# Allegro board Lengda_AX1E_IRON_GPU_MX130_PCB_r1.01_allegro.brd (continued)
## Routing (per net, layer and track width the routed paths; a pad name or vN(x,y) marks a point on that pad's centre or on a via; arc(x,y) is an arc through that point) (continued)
GNDS_SENSE: length 0.6
  TOP w0.102: U3.F3 v1(32.98,37.8)
VDD_GPU: length 27.7
  L3 w0.305: v1(67.46,46.82) 67.59,46.69 67.59,44.89 67.88,44.6 69.67,44.6 71.26,46.18 71.26,60.58 68.81,63.04 v1(66.15,63.04)
  BOTTOM w0.203: R739.1 v1(67.46,46.82)
VDD_GPU_AON: length 195.1
  TOP w0.305: R257.2 21.52,29.05 21.66,28.9 R619.2 R622.2 R643.1 ; R640.1 v1(28.26,32.34) ; R643.1 v1(21.42,27.34) ; R643.1 R617.1
  L3 w0.305: v1(21.42,27.34) 23.16,27.34 25.32,25.18 25.32,17.68 28.01,14.99 36.69,14.99 37.02,14.66 42,14.66 v1(42.09,14.75) 42.2,14.86 47.75,14.86 49.64,12.97 61.52,12.97 62.6,11.89 v1(63.04,11.89) 63.04,17.32 64.2,18.47 64.2,24.52 63.64,25.08 63.64,34.78 66.03,37.17 66.03,42.18 v1(65.44,42.77)
  L6 w0.305: v1(21.42,27.34) 21.02,26.93 19.66,26.93 16.66,23.93 v1(16.66,9.66) ; v1(63.59,56.58) 63.02,56.58 59.84,53.41 59.84,50.96 59.46,50.58 v1(59.28,50.58) 59.28,50.28 59.68,49.89 59.68,47.34 64.25,42.77 v1(65.44,42.77)
  BOTTOM w0.203: R637.1 59.28,50.58 v1(59.28,50.58) ; R647.1 65.27,42.6 v1(65.44,42.77)
  BOTTOM w0.254: v1(21.42,27.34) 22.16,26.6 R642.1
  BOTTOM w0.305: Q36.1 22.68,24.49 22.91,24.72 R645.1 ; Q36.1 23.07,23.35 24.12,22.31 25.2,22.31 25.63,22.74 25.63,25.44 26.79,26.61 R601.2 26.98,28.67 R602.1 27.87,29.56 R636.1 27.87,31.95 v1(28.26,32.34) ; Q36.1 21.09,23.35 20.76,23.68 20.76,26.68 v1(21.42,27.34) 22,27.91 22,29.43 22.26,29.7 Q35.1 ; Q35.1 24.37,29.7 R615.1 ; Q35.1 23.2,30.68 24.02,31.51 R631.2 R641.2 24.23,32.81 21.82,32.81 21.41,33.21 Q34.1 21.41,34.74 21.8,35.13 R614.1 ; v1(42.09,14.75) 41.82,15.02 R37.1 41.39,16.62 40.94,17.08 R41.1 ; R599.1 R594.1 v1(16.66,9.66) ; 62.48,60.06 62.22,60.33 ; 62.22,60.33 62.48,60.33 ; 62.22,60.33 62.2,60.33 ; R100.1 63.28,11.66 v1(63.04,11.89) ; R251.2 31.05,30.07 28.78,32.34 v1(28.26,32.34) ; v1(28.26,32.34) 28.26,32.78 R635.1 27.83,33.21 R634.1 27.84,34.09 R638.1 R639.1 ; 62.2,60.33 62.47,60.6 ; 62.2,60.33 61.85,60.33 61.57,60.61 R750.1
VDD_GPU_MAIN: length 191.7
  TOP w0.305: R28.2 18.57,25.95 v1(19.54,24.98) ; R754.1 v1(60.79,57.81)
  L3 w0.305: v1(19.54,24.98) 19.79,24.73 19.79,21.06 22.31,18.53 22.31,14.59 27.15,9.75 31.28,9.75 32.66,11.13 37.24,11.13 38.06,10.31 40.86,10.31 41.53,10.98 43.84,10.98 45.27,9.56 60.24,9.56 v1(60.31,9.63)
  L3 w0.508: v1(43.23,20.33) 43.46,20.1 45.19,20.1 45.2,20.08 53.63,20.08 54.1,20.55 54.1,22.34 61.28,29.52 61.28,33.61 60.83,34.05 59.12,34.05 58.41,34.77 58.41,38.21 59.46,39.26 59.46,45.99 56.88,48.57 56.88,51.63 59.94,54.69 59.94,57.1 v1(60.3,57.46)
  L6 w0.305: v1(28.36,26.73) 26.61,24.98 v1(19.54,24.98)
  BOTTOM w0.305: v1(19.54,24.98) R479.2 17,25.48 16.24,26.23 14.69,26.23 12.43,23.97 12.43,21.07 12.87,20.64 R480.2 C863.1 U36.8 14.46,13.79 R481.2 14.33,10.95 15.09,10.19 R593.1 15.87,9.58 16.38,9.06 17.69,9.06 18.23,9.6 R598.1 ; Q6.1 60.92,9.03 v1(60.31,9.63) ; R250.2 28.37,26.73 v1(28.36,26.73)
  BOTTOM w0.508: R250.2 33.93,23.9 37.5,20.33 v1(43.23,20.33) 43.24,20.33 49.16,26.24 49.16,34.19 47.79,35.57 R154.2
VDDS_SENSE: length 0.6
  TOP w0.102: U3.F4 v1(32.98,38.6)
1.5S_LGATE: length 2.5
  BOTTOM w0.305: U37.9 11.48,36.29
  BOTTOM w0.635: 11.48,36.29 10.97,36.8 R701.1
1.5S_UGATE: length 2.6
  BOTTOM w0.305: U37.13 14.35,36.29 14.49,36.43
  BOTTOM w0.635: R698.1 15.42,37.36 14.49,36.43
+VSYS_DCIN: length 3.7
  BOTTOM w0.4: 71.03,37.01 71.5,37.48 ; 71.52,37.01 71.03,37.01 71.59,36.45
  BOTTOM w0.406: GR1.2 70.42,37.81 GC1.1 71.03,37.01
  vias: v2(68.03,13.44) v2(68.05,12.67) v2(68.83,13.44) v2(68.82,12.68) v2(72.99,63.47) v2(72.97,62.73) v2(73.8,63.47) v2(73.8,62.73)
CLK_GPU_OE#: length 2.6
  BOTTOM w0.102: R153.2 59.25,7.71 Q6.3 57.72,7.71 GR5.2
CLK_PCIE_GPU_N: length 50.9
  TOP w0.109: U3.AD8 v1(47.86,42.76)
  L3 w0.087: v1(47.86,42.76) 48.2,42.44 48.29,42.45 49.8,42.45 50.3,41.95 55.14,41.95 v1(55.36,42.16)
  BOTTOM w0.109: v1(55.36,42.16) 55.4,42.12 55.87,42.12 56.22,41.76 56.22,39.73 55.25,38.76 55.25,22.73 56.22,21.75 56.22,6.52 55.91,6.2 55.91,2.9 56.05,2.76 GCN1.11
CLK_PCIE_GPU_P: length 50.9
  TOP w0.109: U3.AE8 v1(47.89,41.92)
  L3 w0.087: v1(55.36,41.59) 55.18,41.76 50.23,41.76 49.73,42.26 48.3,42.26 48.21,42.26 v1(47.89,41.92)
  BOTTOM w0.109: v1(55.36,41.59) 55.67,41.9 55.78,41.9 56,41.67 56,39.82 55.03,38.85 55.03,22.64 56,21.66 56,6.61 55.69,6.29 55.69,2.95 55.59,2.85 55.36,2.85 55.25,2.74 GCN1.13
EMC_THERM#: length 1.6
  TOP w0.203: U2.4 29.5,25.59 29.86,25.96 R27.1
FAN_BACK_GPU: length 7.4
  TOP w0.254: GCN9.2 v1(9.37,77.21)
  BOTTOM w0.305: GR428.2 GR429.2 ; GR429.2 10.18,77.35 10.6,77.77 GD10.P ; GR429.2 v1(9.37,77.21)
FAN_PWMIN_GPU: length 126.7
  TOP w0.102: GCN1.4 58.85,2.37 59.27,2.79 v1(59.27,3.32)
  TOP w0.254: GCN9.3 v1(9.45,78.21)
  L3 w0.203: v1(59.27,3.32) 59.12,3.47 57.71,3.47 55.51,5.67 49.91,5.67 48.4,4.16 40.3,4.16 39.38,5.07 17.28,5.07 12.84,9.52 12.84,21.06 7.85,26.05 7.85,30.07 8.99,31.21 8.99,35.41 10.68,37.1 10.68,51.75 11.57,52.63 11.57,66.67 10.74,67.49 10.74,76.91 v1(9.45,78.21)
FAN_VCC_GPU: length 3.2
  TOP w0.406: GCN9.1 v1(9.26,76.21)
  BOTTOM w0.508: v1(9.26,76.21) GC317.2 GFB11.1
FB_CAL_PD_VDDQ: length 6.5
  TOP w0.135: U3.D22 v1(31.3,54.32)
  BOTTOM w0.102: v1(31.3,54.32) 31.07,54.32 30.67,53.92 28.59,53.92 27.15,55.35 R246.2
FB_CAL_PU_GND: length 3.9
  TOP w0.102: U3.C24 30.08,55.61 v1(29.69,56)
  BOTTOM w0.102: R247.2 27.39,56.63 28.36,56.63 28.6,56.39 29.29,56.39 29.69,56 v1(29.69,56)
FB_CAL_TERM_GND: length 2.3
  TOP w0.102: U3.B25 v1(28.88,56.81)
  BOTTOM w0.102: v1(28.88,56.81) 28.22,57.47 R248.2
FB_CLAMP: length 68
  L3 w0.102: v1(19.18,19.32) 19.18,13.37 25.16,7.38 41.1,7.38 41.95,6.53 46.85,6.53 48.11,7.79 58.18,7.79 v1(59.04,6.93)
  BOTTOM w0.102: R600.2 Q25.3 26.33,21.35 25.91,21.77 21.4,21.77 19.18,19.55 v1(19.18,19.32) ; GCN1.3 59.25,2.54 60.05,3.33 60.05,5.92 v1(59.04,6.93)
FB_PLLAVDD: length 1.8
  TOP w0.3: v1(32.88,49.32) 32.88,49.3 U3.F16
  TOP w0.305: v1(39.08,53.27) 39.08,53.85 U3.P22 ; U3.H22 v1(34.57,53.61)
  vias: v1(49.62,54.99)
FB_VREF: length 1.6
  TOP w0.135: U3.D23 v1(30.47,54.34)
  BOTTOM w0.102: TP1.1 30.08,54.34 v1(30.47,54.34)
FBA_CLK0: length 35.1
  TOP w0.127: R177.2 26.1,69.47 v1(26.22,69.59) ; M1.J12 v1(24.8,78.15) ; U3.D24 v1(30.48,55.99)
  L6 w0.104: v1(24.8,78.15) 24.8,78.33 24.87,78.4 25.19,78.4 25.98,77.6 25.98,75.27 26.99,74.26 26.99,71.23 26.47,70.72 26.47,69.84 v1(26.22,69.59)
  BOTTOM w0.127: v1(26.22,69.59) 26.42,69.43 26.42,68.83 28.95,66.29 28.95,64.23 28.82,64.11 27.27,64.11 26.99,63.83 26.99,63.38 27.24,63.13 28.82,63.13 28.95,63 28.95,62.75 28.82,62.62 27.27,62.62 26.99,62.34 26.99,61.89 27.24,61.64 28.82,61.64 28.95,61.52 28.95,60.01 30.09,58.87 30.09,56.57 30.48,56.18 v1(30.48,55.99) ; M1.J12 24.4,78.55 v1(24.8,78.15)
FBA_CLK0#: length 35.2
  TOP w0.127: M1.J11 v1(24.8,78.95) ; U3.D25 v1(30.48,56.81) ; R176.1 26.99,69.46 v1(26.84,69.61)
  L6 w0.104: v1(24.8,78.95) 24.8,78.69 24.88,78.61 25.27,78.61 26.19,77.69 26.19,75.35 27.2,74.35 27.2,71.14 26.68,70.63 26.68,69.77 v1(26.84,69.61)
  BOTTOM w0.127: M1.J11 24.8,78.95 v1(24.8,78.95) ; v1(26.84,69.61) 26.65,69.43 26.65,68.92 29.18,66.39 29.18,64.14 28.92,63.87 27.36,63.87 27.22,63.73 27.22,63.48 27.34,63.36 28.92,63.36 29.18,63.1 29.18,62.65 28.92,62.39 27.36,62.39 27.22,62.25 27.22,61.99 27.34,61.88 28.92,61.88 29.18,61.61 29.18,60.11 29.42,59.87 29.6,59.87 29.75,60.02 29.92,60.02 30.1,59.84 30.1,59.65 29.96,59.51 29.96,59.33 30.33,58.96 30.33,56.97 v1(30.48,56.81)
FBA_CLK1: length 45
  TOP w0.127: v1(59.45,78.96) 59.45,78.96 M2.J12 ; R14.2 57.36,67.55 57.36,67.31 v1(57.55,67.12) ; U3.N22 v1(38.76,54.4)
  L3 w0.104: v1(57.55,67.12) 57.33,67.33 57.33,75.84 58.26,76.77 58.26,77.53 59.18,78.45 59.18,78.69 v1(59.45,78.96)
  BOTTOM w0.127: v1(57.55,67.12) 57.42,66.99 57.42,65.83 55.68,64.09 42.15,64.09 38.85,60.79 38.85,59.3 37.47,57.92 37.47,55.84 38.51,54.79 38.51,54.52 38.63,54.4 v1(38.76,54.4) ; M2.J12 v1(59.45,78.96)
FBA_CLK1#: length 45.2
  TOP w0.127: v1(56.93,67.09) 57.12,67.29 57.12,67.55 R13.1 ; v1(58.66,78.95) 58.66,78.95 M2.J11 ; U3.M22 v1(37.94,54.38)
  L3 w0.104: v1(58.66,78.95) 58.97,78.64 58.97,78.53 58.05,77.62 58.05,76.86 57.12,75.93 57.12,67.29 v1(56.93,67.09)
  BOTTOM w0.127: v1(37.94,54.38) 38.18,54.38 38.28,54.48 38.28,54.69 37.23,55.74 37.23,58.02 38.61,59.4 38.61,60.89 42.05,64.33 55.58,64.33 57.18,65.93 57.18,66.84 v1(56.93,67.09) ; M2.J11 v1(58.66,78.95)
FBA_CMD0: length 23
  TOP w0.135: U3.C27 30.08,58.57 28.76,59.9 28.76,69.22 26.98,71 26.97,71 26.97,76.22 26.64,76.55 v1(24.8,76.55) M1.G12
  BOTTOM w0.135: M1.G12 v1(24.8,76.55)
FBA_CMD1: length 23.5
  TOP w0.135: M1.H10 v1(26.61,77.75) 27.39,76.97 27.39,71.26 29.45,69.21 29.45,59.84 30.45,58.83 30.45,57.57 U3.C26
  BOTTOM w0.135: M1.H10 v1(26.61,77.75)
FBA_CMD2: length 26
  TOP w0.135: M1.H11 25.55,77.41 v1(25.55,77.41) ; U3.E24 v1(31.34,56)
  BOTTOM w0.111: v1(31.34,56) 30.9,56.43 30.9,57.12 30.68,57.34
  BOTTOM w0.135: 30.68,57.34 30.68,67.14 27.06,70.76 27.06,77.07 26.78,77.35 25.61,77.35 v1(25.55,77.41) M1.H11
FBA_CMD3: length 29.2
  TOP w0.135: M1.K11 v1(25.6,78.96) ; U3.F24 v1(32.13,55.16)
  BOTTOM w0.111: 31.13,59.43 31.11,59.41 31.11,57.74 31.77,57.08 31.77,55.52 v1(32.13,55.16)
  BOTTOM w0.135: M1.K11 v1(25.6,78.96) 27.11,78.96 27.53,78.54 27.53,71.16 31.13,67.56 31.13,59.43
FBA_CMD4: length 24.4
  TOP w0.111: U3.D27 30.88,59.01 30.15,59.74
  TOP w0.135: 30.15,59.74 30.15,69.14 27.79,71.5 27.79,78.19 v1(26.62,79.36) M1.K10
  BOTTOM w0.135: M1.K10 v1(26.62,79.36)
FBA_CMD5: length 27.9
  TOP w0.111: U3.D26 31.28,57.6 31.28,58.16 31.22,58.22 31.22,59.24 30.75,59.74
  TOP w0.135: 30.75,59.74 30.75,69.26 28.22,71.79 28.22,78.67 27.13,79.76 v1(24.8,79.76) M1.L12
  BOTTOM w0.135: M1.L12 v1(24.8,79.76)
FBA_CMD6: length 27.7
  TOP w0.111: 31.38,59.64 32.05,58.97 32.05,58.34 31.97,58.26 31.97,57.65 32.12,57.51 32.12,56.86 U3.F25
  TOP w0.135: M1.K4 v1(30.39,79.75) 29.02,79.75 28.61,79.34 28.61,72.06 31.38,69.29 31.38,59.64
  BOTTOM w0.135: M1.K4 v1(30.39,79.75)
FBA_CMD7: length 25.1
  TOP w0.111: U3.F26 32.58,57.41 32.21,57.79 32.21,58.16 32.39,58.34 32.39,59.35 32.03,59.71
  TOP w0.135: 32.03,59.71 32.03,69.26 28.98,72.3 28.98,78.91 v1(29.43,79.36) M1.K5
  BOTTOM w0.135: M1.K5 v1(29.43,79.36)
FBA_CMD8: length 28
  TOP w0.135: U3.F23 v1(32.98,55.2) ; M1.J4 v1(30.4,78.15)
  BOTTOM w0.111: v1(32.98,55.2) 32.98,55.29 32.5,55.77 32.5,59.07 32.19,59.38
  BOTTOM w0.135: M1.J4 v1(30.4,78.15) 29.39,78.15 28.32,77.08 28.32,71.88 32.19,68 32.19,59.38
FBA_CMD9: length 29
  TOP w0.135: M1.J5 v1(29.43,78.55) ; U3.G22 v1(32.98,54.37)
  BOTTOM w0.111: 31.59,59.32 32.08,58.84 32.08,55.78 32.56,55.29 32.56,54.78 v1(32.98,54.37)
  BOTTOM w0.135: M1.J5 29.43,78.56 v1(29.43,78.55) 28.83,78.55 27.93,77.65 27.93,71.46 31.59,67.79 31.59,59.32
FBA_CMD10: length 28.4
  TOP w0.135: M1.H4 v1(30.39,77.35) ; U3.G23 v1(33.8,55.2)
  BOTTOM w0.111: v1(33.8,55.2) 33.41,55.6 33.41,59.43 33.24,59.59
  BOTTOM w0.135: M1.H4 v1(30.39,77.35) 30.39,76.66 30.29,76.56 29.79,76.56 29.13,75.89 29.13,72.42 31.73,69.81 31.92,69.81 32.05,69.94 32.25,69.94 32.44,69.75 32.44,69.56 32.3,69.43 32.3,69.24 32.49,69.05 32.68,69.05 32.84,69.21 33.05,69.21 33.24,69.02 33.24,68.84 33.07,68.67 33.07,68.48 33.78,67.76 33.78,64.34 33.24,63.8 33.24,59.59
FBA_CMD11: length 27.1
  TOP w0.135: M1.H5 v1(29.5,77.45) ; U3.G24 v1(32.99,56)
  BOTTOM w0.111: v1(32.99,56) 32.96,56.04 32.96,59.3 32.66,59.6
  BOTTOM w0.135: 32.66,59.6 32.66,65.2 32.79,65.33 33.13,65.33 33.26,65.46 33.26,65.73 33.13,65.87 32.79,65.87 32.66,66 32.66,66.27 32.79,66.41 33.13,66.41 33.26,66.54 33.26,66.81 33.13,66.95 32.79,66.95 32.66,67.08 32.66,68.28 28.75,72.19 28.75,76.87 29.32,77.45 v1(29.5,77.45) M1.H5
FBA_CMD12: length 26.1
  TOP w0.111: 32.58,59.64 32.75,59.47 32.75,58.17 U3.F27
  TOP w0.135: M1.G3 v1(31.99,77.35) 33.95,77.35 35.17,76.13 35.17,71.32 34.45,70.6 34.26,70.6 33.99,70.87 33.8,70.87 33.61,70.68 33.61,70.49 33.88,70.22 33.88,70.03 33.69,69.84 33.5,69.84 33.22,70.11 33.03,70.11 32.84,69.92 32.84,69.73 33.11,69.46 33.11,69.27 32.58,68.74 32.58,59.64
  BOTTOM w0.135: M1.G3 v1(31.99,77.35)
FBA_CMD13: length 27.1
  TOP w0.111: U3.G25 32.99,56.79 32.99,58.33 33.38,58.71 33.38,59.27 33.22,59.43
  TOP w0.135: 33.22,59.43 33.22,68.19 35.8,70.78 35.8,77.65 35.31,78.14 R240.2 34.97,78.14 v1(32.8,78.14) M1.J2
  BOTTOM w0.135: M1.J2 v1(32.8,78.14)
FBA_CMD14: length 27.4
  TOP w0.111: 33.95,61.13 33.67,60.84 33.67,58.53 33.38,58.24 U3.G27
  TOP w0.135: M1.J3 v1(31.99,78.96) 34.95,78.96 R200.1 35.64,78.98 36.47,78.15 36.47,70.48 33.95,67.96 33.95,61.13
  BOTTOM w0.135: M1.J3 v1(31.99,78.96)
FBA_CMD15: length 30.5
  TOP w0.111: U3.G26 33.8,57.62
  TOP w0.135: 33.8,57.62 33.8,58.25 33.96,58.41 33.96,60.26 34.48,60.78 34.48,67.37 37.06,69.94 37.06,79.14 35.7,80.5 34.62,80.5 33.88,79.76 v1(32,79.76) M1.L3
  BOTTOM w0.135: M1.L3 v1(32,79.76)
FBA_CMD16: length 41.2
  TOP w0.135: U3.M24 v1(37.14,55.2) ; M2.L12 v1(59.44,76.55)
  BOTTOM w0.111: v1(37.14,55.2) 36.97,55.38 36.97,58.75
  BOTTOM w0.135: M2.L12 v1(59.44,76.55) 57.73,76.55 57.38,76.19 57.38,72.38 58.14,71.62 58.14,69.46 53.88,65.19 41.8,65.19 37.73,61.13 37.73,59.52 36.97,58.75
FBA_CMD17: length 42.2
  TOP w0.135: M2.K10 v1(57.58,77.08) ; U3.M23 v1(37.13,54.39)
  BOTTOM w0.111: v1(37.13,54.39) 36.71,54.8 36.71,57.04 36.16,57.59 36.16,58.74
  BOTTOM w0.135: 36.16,58.74 37.17,59.75 37.17,61.51 41.47,65.8 53.8,65.8 57.67,69.68 57.67,71.64 57.04,72.28 57.04,76.54 v1(57.58,77.08) M2.K10
FBA_CMD18: length 42.5
  TOP w0.135: M2.K11 v1(59.46,78.16) ; v1(36.26,56.01) 35.86,55.61 U3.K24
  BOTTOM w0.111: 35.87,59.07 35.87,56.4 v1(36.26,56.01)
  BOTTOM w0.135: 35.87,59.07 36.65,59.85 36.65,62.02 41.12,66.49 53.78,66.49 57.21,69.92 57.21,71.51 56.72,72 56.72,76.85 58.02,78.16 v1(59.46,78.16) 59.46,78.15 M2.K11
FBA_CMD19: length 44.3
  TOP w0.135: M2.H11 v1(58.64,79.76) ; U3.K23 v1(35.47,55.2)
  BOTTOM w0.111: 35.57,59.46 35.57,55.3 v1(35.47,55.2)
  BOTTOM w0.135: 35.57,59.46 36.11,59.99 36.11,62.31 40.92,67.13 53.48,67.13 56.72,70.36 56.72,71.4 56.44,71.68 56.44,78.92 57.27,79.76 v1(58.64,79.76) M2.H11
FBA_CMD20: length 35.6
  TOP w0.111: U3.M27 38.52,58.97
  TOP w0.135: 38.52,58.97 38.52,60.58 44.01,66.07 51.56,66.07 57.09,71.6 57.09,79.19 57.25,79.35 v1(57.63,79.35) M2.H10
  BOTTOM w0.135: M2.H10 v1(57.63,79.35)
FBA_CMD21: length 39.5
  TOP w0.111: 38.06,59.06 37.15,58.14 37.15,57.85 37.54,57.46 U3.M26
  TOP w0.135: 38.06,59.06 38.06,60.85 44.1,66.89 51.54,66.89 56.69,72.04 56.69,79.84 57.41,80.56 v1(59.44,80.56) M2.G12
  BOTTOM w0.135: M2.G12 v1(59.44,80.56)
FBA_CMD22: length 38.9
  TOP w0.111: U3.M25 37.12,56.82 37.12,57.48 36.93,57.67 36.93,57.74 36.92,57.74 36.92,58.33 37.61,59.02
  TOP w0.135: 37.61,59.02 37.61,61.12 44.22,67.74 51.41,67.74 56.29,72.61 56.29,78.92 55.45,79.76 v1(53.85,79.76) M2.H4
  BOTTOM w0.135: M2.H4 v1(53.85,79.76)
FBA_CMD23: length 36.7
  TOP w0.111: U3.K26 36.25,57.59 36.25,58.28 36.1,58.43 36.1,58.74 37.14,59.77
  TOP w0.135: 37.14,59.77 37.14,61.55 44.22,68.64 51.56,68.64 55.89,72.97 55.89,78.64 55.18,79.36 v1(54.84,79.36) M2.H5
  BOTTOM w0.135: M2.H5 54.84,79.36 v1(54.84,79.36)
FBA_CMD24: length 44.7
  TOP w0.135: M2.J4 v1(53.85,78.96) ; U3.K22 v1(35.46,54.4)
  BOTTOM w0.111: v1(35.46,54.4) 35.46,54.64 35.07,55.03 35.07,55.45 35.33,55.72 35.33,58.82 35.04,59.12 35.04,59.58
  BOTTOM w0.135: 35.04,59.58 35.46,60 35.46,62.59 40.51,67.65 53.15,67.65 56.15,70.65 56.15,78.27 55.46,78.96 v1(53.85,78.96) M2.J4
FBA_CMD25: length 42.3
  TOP w0.135: M2.J5 v1(54.81,78.56) ; U3.J23 v1(34.66,55.2)
  BOTTOM w0.111: v1(34.66,55.2) 34.66,55.47 35.06,55.87 35.06,58.58 34.59,59.06
  BOTTOM w0.135: 34.59,59.06 34.59,62.56 40.23,68.2 52.87,68.2 55.85,71.19 55.85,77.99 55.28,78.56 v1(54.81,78.56) 54.25,78.56 M2.J5
FBA_CMD26: length 41
  TOP w0.135: U3.J25 35.04,56.4 v1(34.64,56.8) ; M2.K4 v1(53.85,78.14)
  BOTTOM w0.111: 34.14,58.99 34.64,58.49 v1(34.64,56.8)
  BOTTOM w0.135: 34.14,58.99 34.14,63.04 40.14,69.04 52.87,69.04 55.55,71.72 55.55,77.67 55.05,78.16 53.87,78.16 v1(53.85,78.14) M2.K4
FBA_CMD27: length 40.4
  TOP w0.135: v1(34.64,56.02) 35.06,55.6 U3.J24 ; M2.K5 v1(54.82,77.75)
  BOTTOM w0.111: v1(34.64,56.02) 34.64,56.21 34.23,56.63 34.23,57.21 33.69,57.74
  BOTTOM w0.135: M2.K5 54.81,77.75 v1(54.82,77.75) 55.18,77.39 55.18,72.13 52.64,69.59 39.79,69.59 33.69,63.49 33.69,57.74
FBA_CMD28: length 33.6
  TOP w0.111: 36.68,59.96 35.76,59.04 35.76,58.1 U3.K27
  TOP w0.135: 36.68,59.96 36.68,61.99 44.7,70.02 44.89,70.02 45.64,69.27 45.83,69.27 46.03,69.46 46.03,69.65 45.28,70.4 45.28,70.59 45.47,70.78 45.66,70.78 46.53,69.91 46.72,69.91 46.92,70.1 46.92,70.29 46.04,71.16 46.04,71.36 48.31,73.63 48.31,75.43 50.23,77.35 v1(52.25,77.35) M2.L3
  BOTTOM w0.135: M2.L3 v1(52.25,77.35)
FBA_CMD29: length 33.8
  TOP w0.111: 36.23,60.15 35.48,59.4 35.48,56.78 U3.K25
  TOP w0.135: 36.23,60.15 36.23,62.41 47.5,73.68 47.5,74.21 47.36,74.35 46.87,74.35 46.74,74.48 46.74,74.75 46.87,74.88 47.36,74.88 47.5,75.02 47.5,75.29 47.36,75.42 46.87,75.42 46.74,75.56 46.74,75.83 46.87,75.96 47.36,75.96 47.5,76.1 47.5,76.67 R241.2 49.89,78.47 50.2,78.16 v1(51.46,78.16) M2.J2
  BOTTOM w0.135: M2.J2 v1(51.46,78.16)
FBA_CMD30: length 32.4
  TOP w0.111: 35.55,60.32 35.08,59.86 35.08,58.02 U3.J27
  TOP w0.135: M2.J3 v1(52.26,78.95) 51.79,78.96 49.93,78.96 49.62,79.27 R201.1 47.5,79.27 46.06,77.83 46.06,73.44 35.55,62.92 35.55,60.32
  BOTTOM w0.135: M2.J3 v1(52.26,78.95)
FBA_CMD31: length 34.2
  TOP w0.111: 35,60.49 34.79,60.28 34.79,58.31 34.72,58.24 34.72,57.55 U3.J26
  TOP w0.135: M2.G3 v1(52.25,79.76) 46.98,79.76 45.47,78.25 45.47,73.74 35,63.27 35,60.49
  BOTTOM w0.135: M2.G3 v1(52.25,79.76)
FBA_D0: length 27.2
  TOP w0.135: U3.E18 31.3,51.01 v1(30.49,51.01) ; M1.A4 v1(31.17,71.7)
  L3 w0.108: v1(31.17,71.7) 30.74,71.27 30.74,70.74 26.65,66.65 26.65,57.64 25.96,56.95 25.96,54.98 28.55,52.39 28.9,52.39 29.25,52.04 29.25,51.69 29.5,51.44 30.05,51.44 v1(30.49,51.01)
FBA_D1: length 24.9
  TOP w0.135: U3.F18 v1(32.09,51.02) ; M1.A2 v1(32.87,71.66)
  L3 w0.108: v1(32.09,51.02) 31.67,51.44 31.67,52.02 31.43,52.26 31.13,52.26 30.21,53.18 30.21,53.59 29.29,54.51 29.29,66.21 33.06,69.99 33.06,71.46 v1(32.87,71.66)
FBA_D2: length 30.4
  TOP w0.135: U3.E16 v1(32.09,49.35) ; M1.B4 v1(30.39,72.55)
  L3 w0.108: v1(30.39,72.55) 29.63,71.8 29.63,70.46 25.97,66.79 25.97,57.81 25.33,57.17 25.33,54.85 29.09,51.09 29.81,51.09 30.28,50.62 31.45,50.62 31.7,50.36 31.7,49.97 32.09,49.59 v1(32.09,49.35)
FBA_D3: length 29.9
  TOP w0.135: U3.F17 32.93,50.18 32.93,50.96 v1(32.88,51.01) ; M1.B2 v1(32,72.55)
  L3 w0.108: v1(32,72.55) 32.45,72.1 32.45,70.17 28.29,66.02 28.29,56.9 27.89,56.5 27.62,56.5 27.28,56.17 27.28,55.36 28.73,53.92 29.04,53.92 29.3,53.66 29.3,53.3 29.52,53.08 29.81,53.08 30.06,52.83 30.06,52.43 31.88,50.61 32.53,50.61 32.88,50.97 v1(32.88,51.01)
FBA_D4: length 27.2
  TOP w0.135: U3.D20 v1(31.27,52.67) ; M1.E4 v1(31.19,74.96)
  L3 w0.108: v1(31.19,74.96) 31.33,74.96 31.75,74.54 32.23,74.54 32.41,74.36 32.41,73.13 32.58,72.96 33,72.96 33.86,72.1 33.86,70.01 30.09,66.24 30.09,54.16 30.51,53.74 30.51,53.35 31.18,52.67 v1(31.27,52.67)
FBA_D5: length 25.8
  TOP w0.135: U3.D21 v1(31.29,53.5) ; M1.E2 v1(32.8,74.95)
  L3 w0.108: v1(31.29,53.5) 31.72,53.94 31.72,56.42 32.32,57.02 32.32,67.02 35.28,69.98 35.28,73.39 34.5,74.17 33.58,74.17 v1(32.8,74.95)
FBA_D6: length 31.4
  TOP w0.135: U3.F20 v1(32.94,52.68) ; M1.F4 v1(31.2,76.56)
  L3 w0.108: v1(31.2,76.56) 31.59,76.95 33.02,76.95 33.43,76.54 34.81,76.54 36.79,74.56 36.79,69.84 33.39,66.44 33.39,54.1 32.94,53.64 v1(32.94,52.68)
FBA_D7: length 29.2
  TOP w0.135: U3.E21 v1(32.12,52.68) ; M1.F2 v1(31.99,75.75)
  L3 w0.108: v1(32.12,52.68) 32.58,53.15 32.58,56.55 32.87,56.83 32.87,66.67 35.98,69.78 35.98,74.11 34.32,75.76 33.42,75.76 33.01,76.17 32.41,76.17 v1(31.99,75.75)
FBA_D8: length 33.3
  TOP w0.135: U3.E15 v1(32.11,47.71)
  L3 w0.108: v1(25.05,71.51) 25.05,69.73 23.22,67.9 23.22,53.21 23.43,53 23.58,53 23.78,53.2 23.93,53.2 24.08,53.05 24.08,52.9 23.88,52.7 23.88,52.54 24.04,52.39 24.19,52.39 24.39,52.59 24.54,52.59 24.69,52.44 24.69,52.29 24.5,52.09 24.5,51.93 27.14,49.29 28.36,49.29 28.72,48.93 31.47,48.93 31.71,48.68 31.71,48.11 v1(32.11,47.71)
  BOTTOM w0.135: M3.V11 v1(25.05,71.51)
FBA_D9: length 32.9
  TOP w0.135: U3.D15 v1(31.28,48.54)
  L3 w0.108: v1(31.28,48.54) 30.9,48.15 29.51,48.15 29.18,48.49 27.08,48.49 26.74,48.83 26.59,48.83 26.39,48.63 26.23,48.63 26.08,48.78 26.08,48.93 26.28,49.13 26.28,49.29 26.13,49.44 25.97,49.44 25.77,49.24 25.62,49.24 25.47,49.39 25.47,49.54 25.67,49.74 25.67,49.9 22.62,52.95 22.62,68.81 24.13,70.32 v1(24.13,71.48)
  BOTTOM w0.135: v1(24.13,71.48) 23.6,72.02 M3.V13
FBA_D10: length 34.3
  TOP w0.135: U3.F15 v1(32.13,48.54)
  L3 w0.108: v1(32.13,48.54) 32.13,48.64 31.69,49.08 31.69,49.51 31.44,49.76 27.29,49.76 26.97,50.09 26.97,50.75 26.41,51.3 26.26,51.3 26.07,51.11 25.92,51.11 25.76,51.27 25.76,51.42 25.95,51.61 25.95,51.76 25.8,51.91 25.65,51.91 25.46,51.73 25.31,51.73 25.15,51.88 25.15,52.03 25.34,52.22 25.34,52.37 23.69,54.03 23.69,67.73 24.04,68.09 24.19,68.09 24.3,67.98 24.45,67.98 24.6,68.13 24.6,68.28 24.5,68.39 24.5,68.54 24.65,68.7 24.8,68.7 24.91,68.59 25.06,68.59 25.21,68.74 25.21,68.9 25.11,69 25.11,69.16 25.6,69.65 v1(25.6,72.55)
  BOTTOM w0.135: M3.T11 v1(25.6,72.55)
FBA_D11: length 36.1
  TOP w0.135: U3.F13 v1(32.11,46.9)
  L3 w0.108: v1(23.2,72.55) 23.2,72.03 22.23,71.06 22.07,71.06 21.87,71.26 21.7,71.26 21.55,71.11 21.55,70.97 21.77,70.75 21.77,70.6 21.62,70.44 21.62,51.66 26.07,47.2 29.42,47.2 29.55,47.33 31.65,47.33 v1(32.11,46.9)
  BOTTOM w0.135: M3.T13 v1(23.2,72.55)
FBA_D12: length 39.5
  TOP w0.135: U3.C13 v1(29.68,46.05)
  L3 w0.108: v1(29.68,46.05) 29.44,46.05 29.04,46.45 28.41,46.45 28,46.04 26,46.04 20.43,51.61 20.43,72.93 22.05,74.55 24.38,74.55 v1(24.79,74.96)
  BOTTOM w0.135: M3.N11 v1(24.79,74.96)
FBA_D13: length 39.6
  TOP w0.135: U3.B13 v1(28.88,46.05)
  L3 w0.108: v1(24.01,75.75) 23.61,75.35 22.06,75.35 19.9,73.19 19.9,51.38 25.6,45.68 28.51,45.68 v1(28.88,46.05)
  BOTTOM w0.135: M3.N13 v1(24.01,75.75)
FBA_D14: length 48
  TOP w0.135: U3.E13 v1(31.27,46.06)
  L3 w0.108: v1(25.6,75.76) 25.22,76.16 24.51,76.16 23.74,76.94 21.85,76.94 18.91,74 18.91,50.93 24.97,44.87 29.6,44.87 30.36,45.64 30.85,45.64 v1(31.27,46.06)
  BOTTOM w0.135: M3.M11 v1(25.6,75.76)
FBA_D15: length 42.4
  TOP w0.135: U3.D13 v1(30.48,46.06)
  L3 w0.108: v1(30.48,46.06) 30.29,46.07 29.49,45.28 25.26,45.28 19.38,51.16 19.38,73.5 22.01,76.13 22.78,76.13 v1(23.2,76.54)
  BOTTOM w0.135: v1(23.2,76.54) M3.M13
FBA_D16: length 50.4
  TOP w0.135: M1.V11 25.25,85.01 25.25,85.51 24.86,85.9 v1(24.24,85.9) ; U3.B15 v1(28.79,47.64)
  L6 w0.108: v1(28.79,47.64) 28.3,47.15 26.7,47.15 19.19,54.65 19.19,83.71 21.44,85.96 24.18,85.96 v1(24.24,85.9)
FBA_D17: length 45.6
  TOP w0.135: M1.V13 v1(23.2,84.56) ; U3.C16 v1(29.68,48.54)
  L6 w0.108: v1(23.2,84.56) 23.19,84.57 21.6,84.57 20.05,83.03 20.05,54.92 26.83,48.14 27.95,48.14 28.35,48.54 v1(29.68,48.54)
FBA_D18: length 52
  TOP w0.135: M1.T11 v1(25.6,84.56) ; v1(27.46,46.44) 27.48,46.46 U3.A13
  L6 w0.108: v1(25.6,84.56) 25.6,85.17 24.42,86.34 21.18,86.34 18.76,83.91 18.76,54.46 26.45,46.77 27.13,46.77 v1(27.46,46.44)
FBA_D19: length 47.4
  TOP w0.135: U3.A15 27.54,48.14 v1(27.03,47.64) ; M1.T13 24,84.56 24,85.35 v1(24,85.35)
  L6 w0.108: v1(27.03,47.64) 26.75,47.64 19.62,54.77 19.62,83.3 21.65,85.34 22.99,85.34 23.23,85.1 23.76,85.1 24,85.34 v1(24,85.35)
FBA_D20: length 40.6
  TOP w0.135: U3.B18 v1(28.83,50.17) ; M1.N11 v1(24.79,82.16)
  L6 w0.108: v1(28.83,50.17) 28.43,49.76 27.03,49.76 21.44,55.35 21.44,65.74 21.88,66.18 21.88,78.2 21.68,78.39 21.68,81.01 22.05,81.37 22.4,81.37 22.79,81.76 24.4,81.76 v1(24.79,82.16)
FBA_D21: length 37.2
  TOP w0.135: v1(27.44,50.19) 27.6,50.19 28.03,50.62 U3.A18 ; v1(23.21,81.35) 23.21,81.36 M1.N13
  L6 w0.108: v1(27.44,50.19) 26.93,50.7 26.76,50.7 21.88,55.58 21.88,65.33 22.56,66.01 22.56,67.1 22.67,67.21 23.21,67.21 23.3,67.3 23.3,67.52 23.18,67.64 22.67,67.64 22.56,67.75 22.56,69.97 22.78,70.19 22.78,70.95 22.71,71.02 22.71,71.49 22.78,71.56 22.78,80.93 23.2,81.35 v1(23.21,81.35)
FBA_D22: length 37.8
  TOP w0.135: U3.A19 27.67,52.24 v1(26.47,52.24) ; M1.M11 v1(25.59,81.35)
  L6 w0.108: v1(25.59,81.35) 24.39,80.15 24.39,71.76 24.6,71.56 24.6,69.23 24.7,69.13 25.36,69.13 25.46,69.02 25.46,68.8 25.36,68.69 24.7,68.69 24.6,68.59 24.6,68.37 24.7,68.26 25.36,68.26 25.46,68.15 25.46,67.94 25.36,67.83 24.7,67.83 24.6,67.72 24.6,66.5 22.78,64.69 22.78,55.92 v1(26.47,52.24)
FBA_D23: length 37.4
  TOP w0.135: v1(27.24,51.25) 27.89,51.25 28.13,51.01 29.67,51.01 U3.C19 ; M1.M13 v1(24,80.56)
  L6 w0.108: v1(27.24,51.25) 26.76,51.25 22.31,55.69 22.31,65.03 23.75,66.46 23.75,68.8 23.64,68.91 23.12,68.91 23.01,69.02 23.01,69.23 23.12,69.34 23.64,69.34 23.75,69.45 23.75,70.55 23.59,70.71 23.59,80.15 v1(24,80.56)
FBA_D24: length 41.6
  TOP w0.135: U3.B24 v1(28.88,55.99)
  L6 w0.108: v1(28.88,55.99) 28.49,56.38 28.49,57.79 28.72,58.03 29.91,58.03 30.12,58.24 30.12,62.08 38.64,70.6 38.64,81.55 35.17,85.02 30.73,85.02 v1(30.38,85.37)
  BOTTOM w0.135: M3.A4 v1(30.38,85.37)
FBA_D25: length 40.2
  TOP w0.135: U3.C23 v1(30.48,55.14)
  L6 w0.108: v1(30.48,55.14) 30.89,55.55 30.89,62.09 39.19,70.38 39.19,81.8 35.06,85.93 32.63,85.93 v1(32.38,85.72)
  BOTTOM w0.135: M3.A2 v1(32.38,85.72)
FBA_D26: length 38.4
  TOP w0.111: U3.A25 28.11,56.77 28.11,57.66 v1(28.88,58.48)
  L6 w0.108: v1(28.88,58.48) 29.31,58.91 29.31,61.98 38.1,70.77 38.1,81.44 35,84.54 33.36,84.54 32.98,84.16 31.59,84.16 v1(31.2,84.55)
  BOTTOM w0.135: M3.B4 v1(31.2,84.55)
FBA_D27: length 37.5
  TOP w0.111: v1(27.71,57.08) 27.76,56.58 28.34,56 28.34,55.75 U3.A24
  L6 w0.108: v1(32,83.75) 32.38,83.37 33.22,83.37 33.59,83.74 34.91,83.74 37.62,81.02 37.62,70.91 28.09,61.38 28.09,57.46 v1(27.71,57.08)
  BOTTOM w0.135: M3.B2 v1(32,83.75)
FBA_D28: length 37.9
  TOP w0.135: U3.A21 v1(28.09,53.49)
  L6 w0.108: v1(28.09,53.49) 28.09,54.09 26.42,55.76 26.42,62.24 36.06,71.88 36.06,79.72 34.41,81.36 33.52,81.36 33.13,81.75 31.58,81.75 31.22,81.4 31.22,81.37 v1(31.2,81.36)
  BOTTOM w0.135: M3.E4 v1(31.2,81.36)
FBA_D29: length 37.4
  TOP w0.135: U3.B21 28.81,52.63 28.09,52.63 26.66,54.06 26.66,54.8 v1(26.72,54.86)
  L6 w0.108: v1(32.78,81.36) 33.24,80.9 33.24,80.16 33.57,79.84 34.79,79.84 35.49,79.15 35.49,72.03 25.96,62.5 25.96,55.62 v1(26.72,54.86)
  BOTTOM w0.135: M3.E2 v1(32.78,81.36)
FBA_D30: length 35.1
  TOP w0.135: U3.C20 v1(29.68,52.68)
  L6 w0.108: v1(30.39,80.55) 29.95,80.12 29.95,73.55 29.95,73.54 29.95,73.23 29.95,73.22 29.95,68.29 24.1,62.44 24.1,56.32 27.74,52.68 v1(29.68,52.68)
  BOTTOM w0.135: M3.F4 v1(30.39,80.55)
FBA_D31: length 38.1
  TOP w0.135: U3.C21 v1(29.69,53.49)
  L6 w0.108: v1(32,80.56) 32.03,80.54 32.03,80.53 33.61,78.95 34.74,78.95 34.95,78.73 34.95,72.25 24.56,61.85 24.56,56.41 27.91,53.06 29.25,53.06 v1(29.69,53.49)
  BOTTOM w0.135: M3.F2 v1(32,80.56)
FBA_D32: length 29.1
  TOP w0.135: U3.R22 v1(39.62,53.54)
  L3 w0.108: v1(39.62,53.54) 40.04,53.97 40.04,55.35 40.27,55.58 40.56,55.58 40.86,55.88 40.86,63.56 45.5,68.2 51.85,68.2 53.76,70.11 53.76,71.69 v1(53.84,71.76)
  BOTTOM w0.135: M4.A4 v1(53.84,71.76)
FBA_D33: length 26.3
  TOP w0.135: U3.R24 v1(40.42,56)
  L3 w0.108: v1(52.23,71.74) 52.51,71.47 52.51,69.61 51.55,68.65 44.72,68.65 40.03,63.96 40.03,56.39 v1(40.42,56)
  BOTTOM w0.135: M4.A2 v1(52.23,71.74)
FBA_D34: length 30
  TOP w0.135: U3.T22 v1(40.43,54.37)
  L3 w0.108: v1(53.84,73.36) 54.27,72.93 54.27,69.87 52.24,67.84 46.19,67.84 41.39,63.04 41.39,56.57 41.66,56.3 41.66,55.84 41.41,55.6 41.09,55.6 40.86,55.37 40.86,54.81 v1(40.43,54.37)
  BOTTOM w0.135: M4.B4 v1(53.84,73.36)
FBA_D35: length 27.1
  TOP w0.135: U3.R23 v1(39.6,55.18)
  L3 w0.108: v1(39.6,55.18) 39.21,55.57 39.21,57.1 38.71,57.6 38.71,58.41 38.38,58.74 38.38,64.02 46.91,72.55 v1(51.45,72.55)
  BOTTOM w0.135: M4.B2 v1(51.45,72.55)
FBA_D36: length 32
  TOP w0.135: U3.N25 v1(37.94,56.79)
  L3 w0.108: v1(37.94,56.79) 37.69,56.79 36.15,58.34 36.15,58.89 36.46,59.2 36.46,65.35 46.87,75.76 50.87,75.76 51.28,75.35 52.67,75.35 53.06,75.75 v1(53.06,75.76)
  BOTTOM w0.135: M4.E4 v1(53.06,75.76)
FBA_D37: length 28.7
  TOP w0.135: U3.N26 v1(37.94,57.6)
  L3 w0.108: v1(37.94,57.6) 36.98,58.56 36.98,65 46.94,74.96 50.87,74.96 51.27,74.56 51.85,74.56 v1(52.25,74.96)
  BOTTOM w0.135: M4.E2 v1(52.25,74.96)
FBA_D38: length 38.2
  TOP w0.135: U3.N23 v1(38.78,55.21)
  L3 w0.108: v1(38.78,55.21) 37.97,55.21 36.78,56.4 36.08,56.4 35.13,57.35 35.13,66.24 46.23,77.34 51.51,77.34 51.89,76.95 53.47,76.95 v1(53.86,76.56)
  BOTTOM w0.135: M4.F4 v1(53.86,76.56)
FBA_D39: length 32.1
  TOP w0.135: U3.N24 v1(37.94,55.99)
  L3 w0.108: v1(51.44,76.55) 46.39,76.55 35.81,65.96 35.81,58.03 37.84,55.99 v1(37.94,55.99)
  BOTTOM w0.135: M4.F2 v1(51.44,76.55)
FBA_D40: length 32.6
  TOP w0.135: v1(59.16,71.28) 59.16,72.05 M2.V11 ; U3.V23 v1(42.08,55.19)
  L3 w0.108: v1(42.08,55.19) 42.3,55.19 43.04,55.94 43.04,57.6 44.09,58.65 44.09,61.73 48.08,65.72 53.31,65.72 53.42,65.61 53.42,64.79 53.52,64.69 53.74,64.69 53.85,64.79 53.85,65.61 53.95,65.72 58.31,65.72 59.04,66.45 59.04,71.17 v1(59.16,71.28)
FBA_D41: length 35.2
  TOP w0.135: M2.V13 60.65,71.51 61.01,71.15 v1(61.14,71.15) ; U3.V22 v1(42.9,54.36)
  L3 w0.108: v1(61.14,71.15) 61.14,65.63 58.56,63.05 49.5,63.05 49.4,62.94 49.4,61.96 49.29,61.85 49.07,61.85 48.96,61.96 48.96,62.94 48.86,63.05 47.32,63.05 46.67,62.4 46.67,58.67 44.12,56.12 44.12,55.73 43.97,55.58 43.53,55.58 43.34,55.38 43.34,54.8 v1(42.9,54.36)
FBA_D42: length 33.2
  TOP w0.135: U3.T23 v1(41.24,54.4) ; M2.T11 v1(58.65,72.56)
  L3 w0.108: v1(58.65,72.56) 58.18,72.09 58.18,68.17 58.61,67.73 58.61,66.64 58.09,66.12 47.71,66.12 43.6,62 43.6,58.84 42.76,58.01 42.76,56.07 42.3,55.6 41.94,55.6 41.67,55.33 41.67,54.82 v1(41.24,54.4)
FBA_D43: length 35
  TOP w0.135: U3.U22 v1(42.06,53.56) ; M2.T13 v1(61.05,72.56)
  L3 w0.108: v1(61.05,72.56) 61.52,72.1 61.52,70.76 61.62,70.66 61.62,64.89 58.74,62.01 51.52,62.01 49.47,59.95 49.32,59.95 49.13,60.14 48.97,60.14 48.82,59.99 48.82,59.84 49.01,59.65 49.01,59.49 48.36,58.84 47.47,58.84 44.97,56.34 44.97,55.77 44.79,55.59 44.37,55.59 44.14,55.37 44.14,54.16 43.96,53.98 43.51,53.98 43.09,53.56 v1(42.06,53.56)
FBA_D44: length 39.1
  TOP w0.135: M2.N11 v1(59.45,74.95) ; U3.Y24 v1(44.54,55.2)
  L3 w0.108: v1(59.45,74.95) 59.86,75.36 61.32,75.36 61.73,75.77 62.44,75.77 63.37,74.83 63.37,65.56 58.98,61.17 51.84,61.17 48.31,57.63 48.31,56.66 46.43,54.79 44.96,54.79 v1(44.54,55.2)
FBA_D45: length 34
  TOP w0.135: M2.N13 60.65,75.35 v1(61.04,74.96) ; U3.AA24 v1(45.37,55.2)
  L3 w0.108: v1(61.04,74.96) 62.23,74.96 62.41,74.78 62.41,65.12 58.85,61.56 51.61,61.56 48.37,58.32 47.8,58.32 47.22,57.74 47.22,57.16 46.46,56.4 46.08,56.4 45.83,56.16 45.83,55.66 v1(45.37,55.2)
FBA_D46: length 45.9
  TOP w0.135: U3.Y22 v1(43.73,53.58) ; M2.M11 v1(58.65,75.76)
  L3 w0.108: v1(58.65,75.76) 59.04,76.15 59.57,76.15 59.59,76.17 59.6,76.17 59.82,76.39 59.82,76.4 59.86,76.43 59.86,76.81 60.01,76.96 61.38,76.96 61.77,77.35 62.66,77.35 64.69,75.32 64.69,65.83 59.22,60.36 52.16,60.36 49.89,58.08 49.89,56.29 46.69,53.1 44.22,53.1 v1(43.73,53.58)
FBA_D47: length 39
  TOP w0.135: U3.AA23 v1(44.56,54.4) ; M2.M13 v1(61.06,76.56)
  L3 w0.108: v1(61.06,76.56) 62.44,76.56 63.8,75.2 63.8,65.46 59.08,60.74 51.96,60.74 48.78,57.56 48.78,56.64 46.04,53.9 45.06,53.9 v1(44.56,54.4)
FBA_D48: length 46.1
  TOP w0.111: U3.AD27 48.7,59.22 48.7,60.56 v1(48.29,60.98)
  L6 w0.108: v1(59.46,85.37) 60.21,86.12 62.32,86.12 65.02,83.42 65.02,69.51 61.79,66.27 61.79,65.08 58.84,62.13 49.45,62.13 v1(48.29,60.98)
  BOTTOM w0.135: M4.V11 59.05,84.96 v1(59.46,85.37)
FBA_D49: length 46.2
  TOP w0.111: U3.AB25 45.39,56.79 45.39,57.4 45.6,57.6 46.01,57.6 46.23,57.82 46.23,58.95 46.43,59.15 46.43,60.35 v1(47.43,61.36)
  L6 w0.108: v1(47.43,61.36) 49.18,63.1 58.89,63.1 60.5,64.71 60.5,65.58 64.59,69.68 64.59,83.2 62.01,85.78 61.46,85.78 v1(61.05,85.38)
  BOTTOM w0.135: M4.V13 60.65,84.97 v1(61.05,85.38)
FBA_D50: length 48.9
  TOP w0.111: v1(48.26,59.52) 48.26,59.35 47.09,58.18 47.09,57.74 47.48,57.35 U3.AD26
  L6 w0.108: v1(48.26,59.52) 48.47,59.52 50.52,61.56 58.9,61.56 62.24,64.9 62.24,66.16 65.46,69.37 65.46,83.6 62.59,86.47 59.94,86.47 59.05,85.57 59.05,84.96 v1(58.65,84.56)
  BOTTOM w0.135: M4.T11 59.05,84.16 v1(58.65,84.56)
FBA_D51: length 45.1
  TOP w0.111: 47.86,62.1 47.86,59.43 46.78,58.35 46.78,57.68 47.05,57.41 47.05,56.81 U3.AC25
  TOP w0.135: 47.86,62.1 47.86,62.14 v1(47.44,62.57)
  L6 w0.108: v1(47.44,62.57) 48.32,63.45 58.61,63.45 60.06,64.9 60.06,65.73 64.19,69.86 64.19,82.9 62.11,84.97 61.46,84.97 v1(61.04,84.56)
  BOTTOM w0.135: M4.T13 v1(61.04,84.56)
FBA_D52: length 41.6
  TOP w0.111: U3.AA27 44.98,58.25 45.46,58.73 45.46,60.77 v1(46.01,61.24)
  L6 w0.108: v1(46.01,61.24) 46.01,63.59 48.5,66.08 57.94,66.08 58.72,66.87 59.36,66.87 62.84,70.35 62.84,81.91 62.2,82.54 59.85,82.54 v1(59.45,82.15)
  BOTTOM w0.135: M4.N11 v1(59.45,82.15)
FBA_D53: length 40.9
  TOP w0.111: U3.AA26 44.98,57.37 45.38,57.77 45.38,58.23 45.86,58.7 45.86,59.31 v1(46.01,59.46)
  L6 w0.108: v1(60.23,81.35) 60.63,81.75 62.17,81.75 62.42,81.5 62.42,70.54 59.49,67.61 49.36,67.61 45.54,63.79 45.54,59.92 v1(46.01,59.46)
  BOTTOM w0.135: M4.N13 v1(60.23,81.35)
FBA_D54: length 41
  TOP w0.111: U3.W26 43.54,57.2 44.23,57.89 44.23,59.94 v1(44.99,60.69)
  L6 w0.108: v1(58.64,81.35) 58.64,81.27 58.95,80.96 60.88,80.96 60.89,80.96 61.28,80.96 61.47,80.76 61.47,71.38 61.57,71.28 61.57,70.39 59.14,67.96 48.88,67.96 45.05,64.13 45.05,60.75 v1(44.99,60.69)
  BOTTOM w0.135: M4.M11 v1(58.64,81.35)
FBA_D55: length 38.6
  TOP w0.135: U3.Y25 v1(44.56,55.99)
  L6 w0.108: v1(61.03,80.55) 61.03,80.55 60.64,80.16 60.64,70.21 58.78,68.34 48.4,68.34 44.56,64.51 v1(44.56,55.99)
  BOTTOM w0.135: M4.M13 v1(61.03,80.55)
FBA_D56: length 41.8
  TOP w0.135: U3.R26 39.43,57.79 v1(39.1,57.79) ; M2.A4 v1(53.07,85.41)
  L6 w0.108: v1(53.07,85.41) 51.71,86.77 47.02,86.77 43.13,82.88 43.13,73.42 37.67,67.96 37.67,59.22 v1(39.1,57.79)
FBA_D57: length 39.7
  TOP w0.135: U3.T25 v1(40.43,56.8) ; M2.A2 v1(51.37,85.45)
  L6 w0.108: v1(51.37,85.45) 50.91,85.91 47.26,85.91 43.68,82.32 43.68,73.3 38.24,67.86 38.24,59.6 38.99,58.85 39.61,58.85 39.86,58.6 39.86,57.37 v1(40.43,56.8)
FBA_D58: length 36.3
  TOP w0.135: v1(39.45,60.6) 39.35,60.6 38.97,60.23 38.97,58.63 U3.N27 ; M2.B4 v1(53.04,83.76)
  L6 w0.108: v1(39.45,60.6) 39.46,67.58 45,73.13 45,81.12 48.44,84.55 50.67,84.55 51.05,84.17 52.63,84.17 v1(53.04,83.76)
FBA_D59: length 36.7
  TOP w0.135: U3.R27 40.02,58.82 v1(39.44,59.4) ; M2.B2 v1(52.25,84.56)
  L6 w0.108: v1(52.25,84.56) 51.82,84.99 50.68,84.99 50.39,85.27 47.87,85.27 44.22,81.62 44.22,73.18 38.87,67.84 38.87,59.96 v1(39.44,59.4)
FBA_D60: length 33.6
  TOP w0.111: v1(41.85,60.12) 42.52,59.46 42.52,58.74 42.89,58.37 42.89,57.71 42.5,57.33 U3.V26
  TOP w0.135: v1(53.05,82.15) M2.E4
  L6 w0.108: v1(41.85,60.12) 41.42,60.56 41.42,67.56 46.91,73.06 46.91,79.61 49.46,82.15 50.7,82.15 51.12,82.57 52.63,82.57 v1(53.05,82.15)
FBA_D61: length 30.4
  TOP w0.111: v1(41.86,58.9) 42.5,58.26 U3.V27
  TOP w0.135: M2.E2 v1(52.26,81.36)
  L6 w0.108: v1(41.86,58.9) 42.31,59.35 42.31,67.83 48.04,73.56 48.04,79.73 49.65,81.34 50.86,81.34 51.3,81.78 51.84,81.78 v1(52.26,81.36)
FBA_D62: length 28.9
  TOP w0.111: U3.W27 43.3,58.61 v1(42.94,58.92)
  TOP w0.135: M2.F4 v1(53.05,80.55)
  L6 w0.108: v1(53.05,80.55) 52.64,80.15 51.87,80.15 51.5,79.78 49.98,79.78 49.37,79.16 49.37,73.61 43.37,67.61 43.37,59.15 43.14,58.92 v1(42.94,58.92)
FBA_D63: length 30.5
  TOP w0.111: U3.W25 42.88,56.82 42.88,57.31 43.2,57.63 43.59,57.63 43.82,57.86 43.82,58.62 43.39,59.05 43.39,60.34 v1(42.94,60.75)
  TOP w0.135: M2.F2 v1(51.46,80.56)
  L6 w0.108: v1(51.46,80.56) 49.72,80.56 48.68,79.51 48.68,73.49 42.87,67.67 42.87,60.83 v1(42.94,60.75)
FBA_DBI0: length 27.7
  TOP w0.135: M1.D2 v1(31.99,74.15) ; v1(29.69,51.87) 30.43,51.87 U3.D19
  L3 w0.108: v1(29.69,51.87) 29.7,52.1 28.48,53.32 28.48,53.67 26.62,55.53 26.62,56.79 27.16,57.33 27.16,65.71 31.6,70.15 31.6,73.76 v1(31.99,74.15)
FBA_DBI1: length 37.5
  TOP w0.135: U3.D14 v1(31.31,46.88)
  L3 w0.108: v1(23.19,74.15) 22.81,73.77 22.15,73.77 21.11,72.73 21.11,51.59 25.84,46.86 29.16,46.86 29.55,46.47 30.9,46.47 v1(31.31,46.88)
  BOTTOM w0.135: M3.P13 v1(23.19,74.15)
FBA_DBI2: length 42.9
  TOP w0.135: M1.P13 v1(23.19,82.96) ; U3.C17 v1(30.49,49.37)
  L6 w0.108: v1(30.49,49.37) 30.05,48.94 28.69,48.94 28.28,49.35 26.86,49.35 20.97,55.24 20.97,82.11 21.81,82.96 v1(23.19,82.96)
FBA_DBI3: length 38.7
  TOP w0.135: U3.C22 29.62,54.37 29.14,54.37 28.81,54.69 28.63,54.69 v1(28.21,55.11)
  L6 w0.108: v1(28.21,55.11) 28.15,55.05 27.61,55.05 26.82,55.84 26.82,61.68 36.53,71.4 36.53,80.15 34.54,82.14 33.58,82.14 33.16,82.55 32.4,82.55 v1(31.99,82.14)
  BOTTOM w0.135: M3.D2 v1(31.99,82.14)
FBA_DBI4: length 27.9
  TOP w0.135: U3.P24 v1(38.74,56)
  L3 w0.108: v1(51.44,74.16) 47.32,74.16 37.59,64.43 37.59,58.7 38.37,57.92 38.37,56.37 v1(38.74,56)
  BOTTOM w0.135: M4.D2 v1(51.44,74.16)
FBA_DBI5: length 33.6
  TOP w0.135: M2.P13 v1(61.05,74.15) ; U3.W24 v1(43.72,55.99)
  L3 w0.108: v1(61.05,74.15) 60.66,73.76 60.66,65.8 58.37,63.51 48.38,63.51 48.27,63.61 48.27,63.82 48.16,63.92 47.95,63.92 47.84,63.82 47.84,63.61 47.73,63.51 47.22,63.51 45.43,61.72 45.43,57.92 43.72,56.22 v1(43.72,55.99)
FBA_DBI6: length 43.6
  TOP w0.111: v1(44.98,58.88) 44.55,58.52 44.55,56.83 U3.AA25
  L6 w0.108: v1(44.98,58.88) 46.03,58.88 46.49,59.34 46.49,63.25 48.86,65.61 58.13,65.61 58.86,66.35 59.46,66.35 63.26,70.15 63.26,82.23 62.15,83.33 61.43,83.33 v1(61.06,82.96)
  BOTTOM w0.135: M4.P13 v1(61.06,82.96)
FBA_DBI7: length 35
  TOP w0.111: U3.U25 41.25,56.81 41.25,57.35 41.47,57.56 41.47,59.29 v1(40.46,60.3)
  TOP w0.135: M2.D2 v1(52.26,82.96)
  L6 w0.108: v1(52.26,82.96) 51.86,83.36 51.11,83.36 50.7,82.95 48.84,82.95 46.33,80.43 46.33,73.08 40.9,67.65 40.9,60.72 v1(40.46,60.3)
FBA_DEBUG0: length 8.9
  TOP w0.102: U3.F22 32.16,54.32 v1(32.16,54.36)
  BOTTOM w0.102: R194.1 27.6,53.08 30.2,53.08 31.04,53.92 31.72,53.92 v1(32.16,54.36)
FBA_DEBUG1: length 2
  TOP w0.135: U3.J22 v1(34.66,54.4)
  BOTTOM w0.102: R197.1 33.84,53.57 v1(34.66,54.4)
FBA_EDC0: length 26.4
  TOP w0.135: M1.C2 v1(32.81,73.35) ; U3.E19 v1(32.08,51.85)
  L3 w0.108: v1(32.81,73.35) 32.83,73.37 33.97,73.37 34.6,72.75 34.6,70.09 30.89,66.38 30.89,54.47 30.89,54.15 30.89,54.15 30.89,53.3 31.09,53.1 31.49,53.1 31.7,52.89 31.7,52.47 32.08,52.1 v1(32.08,51.85)
FBA_EDC1: length 36.2
  TOP w0.135: U3.C15 v1(30.51,47.72)
  L3 w0.108: v1(30.51,47.72) 29.52,47.72 29.09,48.15 26.1,48.15 24.79,49.46 24.79,49.61 24.95,49.78 24.95,49.93 24.8,50.08 24.65,50.08 24.48,49.92 24.33,49.92 24.12,50.13 24.12,50.29 24.31,50.48 24.31,50.63 24.15,50.78 24,50.78 23.81,50.59 23.66,50.59 23.5,50.74 23.5,50.9 23.71,51.1 23.71,51.24 23.55,51.39 23.39,51.39 23.2,51.2 23.05,51.2 22.89,51.36 22.89,51.51 23.12,51.74 23.12,51.86 22.97,52.02 22.79,52.02 22.59,51.81 22.44,51.81 22.12,52.13 22.12,69.65 23.55,71.07 23.55,71.58 23.98,72.01 v1(23.98,73.35)
  BOTTOM w0.135: M3.R13 v1(23.98,73.35)
FBA_EDC2: length 44.3
  TOP w0.135: v1(24,83.75) 24,83.74 M1.R13 ; U3.B16 28.9,48.55 28.26,48.55 27.94,48.87 v1(27.88,48.87)
  L6 w0.108: v1(24,83.75) 23.99,83.75 21.62,83.75 21.61,83.74 21.33,83.74 20.49,82.9 20.49,55.03 27.02,48.5 27.5,48.5 v1(27.88,48.87)
FBA_EDC3: length 37.8
  TOP w0.135: v1(27.75,55.47) 27.75,55.46 27.75,54.75 28.22,54.29 28.69,54.29 29.08,53.9 U3.B22
  L6 w0.108: v1(27.75,55.47) 27.31,55.91 27.31,61.48 37.08,71.25 37.08,80.63 34.76,82.95 v1(32.8,82.95)
  BOTTOM w0.135: M3.C2 v1(32.8,82.95)
FBA_EDC4: length 27.5
  TOP w0.135: U3.R25 v1(39.6,56.8)
  L3 w0.108: v1(39.6,56.8) 39.64,56.84 39.64,58.53 39.03,59.14 39.03,63.84 44.3,69.11 51.17,69.11 51.84,69.77 51.84,72.94 v1(52.25,73.35)
  BOTTOM w0.135: M4.C2 v1(52.25,73.35)
FBA_EDC5: length 39.5
  TOP w0.135: M2.R13 v1(60.24,73.36) ; U3.W23 v1(42.91,55.2)
  L3 w0.108: v1(60.24,73.36) 59.84,72.96 59.84,66.68 58.49,65.33 56.81,65.33 55.77,64.29 52.82,64.29 52.71,64.4 52.71,65.02 52.61,65.13 52.39,65.13 52.28,65.02 52.28,64.4 52.17,64.29 51.96,64.29 51.85,64.4 51.85,65.02 51.74,65.13 51.53,65.13 51.42,65.02 51.42,64.4 51.31,64.29 51.09,64.29 50.99,64.4 50.99,65.02 50.88,65.13 50.66,65.13 50.55,65.02 50.55,64.4 50.45,64.29 50.23,64.29 50.12,64.4 50.12,65.02 50.01,65.13 49.8,65.13 49.69,65.02 49.69,64.4 49.58,64.29 49.37,64.29 49.26,64.4 49.26,65.02 49.15,65.13 48.94,65.13 48.83,65.02 48.83,64.4 48.72,64.29 47.31,64.29 44.6,61.58 44.6,58.33 43.32,57.05 43.32,55.79 42.91,55.38 v1(42.91,55.2)
FBA_EDC6: length 43.8
  TOP w0.111: v1(47.44,60.17) 46.87,59.61 46.87,59.08 46.52,58.74 46.52,57.69 46.02,57.2 U3.AB26
  L6 w0.108: v1(47.44,60.17) 47.04,60.57 47.04,62.98 49.06,65 58.17,65 59.02,65.86 59.64,65.86 63.69,69.91 63.69,82.56 62.09,84.16 60.62,84.16 60.26,83.8 v1(60.26,83.76)
  BOTTOM w0.135: M4.R13 v1(60.26,83.76)
FBA_EDC7: length 34.1
  TOP w0.111: v1(40.45,59.04) 41.21,58.28 41.21,57.78 40.82,57.4 U3.T26
  TOP w0.135: M2.C2 v1(51.44,83.76)
  L6 w0.108: v1(40.45,59.04) 40.05,59.44 40.05,67.52 45.8,73.27 45.8,80.83 48.73,83.76 v1(51.44,83.76)
FBA_VREF_FET_L: length 2.6
  TOP w0.4: R179.2 15.56,84.24 16.27,84.94 Q7.3
FBA_VREFC: length 78.2
  TOP w0.3: v1(22.33,78.18) 22.42,78.18 M1.J14
  TOP w0.305: v1(22.33,78.18) 22.18,78.18 21.79,78.57 ; 62.34,78.88 61.97,78.88 v1(61.91,78.93) M2.J14
  TOP w0.4: R180.2 19.63,78.63 19.33,78.94 R178.2 18.76,79.76 17.06,81.46 R179.1 17.06,84.15 17.67,84.75 17.67,87.69 18.88,88.91 62.99,88.91 65.05,86.85 65.05,79.33 64.64,78.93
  TOP w0.406: 21.79,78.57 21.73,78.63 C542.1 20.17,78.63 R180.2 ; 62.34,78.88 C3.1 64.59,78.88 64.64,78.93
  BOTTOM w0.4: M1.J14 22.7,78.56 v1(22.33,78.18) 22.27,78.12 21.3,78.12 C6.1
  BOTTOM w0.406: C9.1 63.04,78.93 v1(61.91,78.93) M2.J14
FBA_WCK01: length 31.9
  TOP w0.127: U3.D18 v1(30.49,50.21) ; M1.D4 v1(30.4,74.16)
  L3 w0.104: v1(30.49,50.21) 30.25,50.21 29.7,50.76 28.85,50.76 24.57,55.04 24.57,66.42 28.15,70 28.15,73.07 29.39,74.31 30.25,74.31 v1(30.4,74.16)
  BOTTOM w0.127: M1.D4 v1(30.4,74.16)
FBA_WCK01#: length 32
  TOP w0.127: U3.C18 v1(29.68,50.22) ; M1.D5 v1(30.4,74.96)
  L3 w0.104: v1(29.68,50.22) 29.68,50.45 29.58,50.55 28.77,50.55 24.37,54.95 24.37,66.51 27.94,70.08 27.94,73.16 29.3,74.52 29.95,74.52 v1(30.4,74.96)
  BOTTOM w0.127: M1.D5 v1(30.4,74.96)
FBA_WCK23: length 43.6
  TOP w0.127: U3.D17 v1(31.31,50.2) ; M1.P4 v1(30.4,82.16)
  L6 w0.104: v1(30.4,82.16) 30.08,82.48 29.33,82.48 29.01,82.17 29.01,69.23 23.57,63.78 23.57,56.14 27.66,52.05 27.82,52.05 27.88,52.11 28.04,52.11 28.18,51.96 28.18,51.83 28.11,51.76 28.11,51.6 28.28,51.43 29.99,51.43 30.15,51.6 30.81,51.6 31.13,51.28 31.13,51.15 31.23,51.04 31.49,51.04 31.6,50.93 31.6,50.72 31.51,50.63 31.23,50.63 31.13,50.52 31.13,50.26 31.19,50.2 v1(31.31,50.2)
  BOTTOM w0.127: M1.P4 v1(30.4,82.16)
FBA_WCK23#: length 43.8
  TOP w0.127: U3.D16 v1(31.3,49.36) ; M1.P5 v1(30.4,82.95)
  L6 w0.104: v1(30.4,82.95) 30.13,82.69 29.24,82.69 28.81,82.25 28.81,69.31 23.36,63.87 23.36,56.06 28.19,51.22 30.07,51.22 30.24,51.39 30.72,51.39 30.92,51.19 30.92,49.74 v1(31.3,49.36)
  BOTTOM w0.127: M1.P5 v1(30.4,82.95)
FBA_WCK45: length 33.1
  TOP w0.127: M2.P4 v1(53.85,74.95) ; U3.T24 v1(41.25,55.17)
  L6 w0.104: v1(41.25,55.17) 41.24,55.45 41.67,55.88 41.67,57.13 41.8,57.26 42.57,57.26 44.07,58.76 44.07,65.1 48.2,69.22 54,69.22 56,71.22 56,73.99 55.36,74.64 54.16,74.64 v1(53.85,74.95)
  BOTTOM w0.127: M2.P4 v1(53.85,74.95)
FBA_WCK45#: length 33
  TOP w0.127: U3.U24 v1(41.24,56) ; M2.P5 v1(53.85,74.16)
  L6 w0.104: v1(41.24,56) 41.35,56 41.47,56.11 41.47,56.4 41.36,56.5 41.14,56.5 41.03,56.61 41.03,56.81 41.14,56.92 41.36,56.92 41.47,57.02 41.47,57.22 41.71,57.46 42.48,57.46 42.71,57.69 42.71,57.84 42.59,57.95 42.59,58.1 42.74,58.25 42.88,58.25 43,58.13 43.15,58.13 43.87,58.85 43.87,65.18 48.11,69.43 53.91,69.43 55.79,71.3 55.79,73.91 55.27,74.43 54.12,74.43 v1(53.85,74.16)
  BOTTOM w0.127: M2.P5 v1(53.85,74.16)
FBA_WCK67: length 38.8
  TOP w0.127: M2.D4 v1(53.85,82.95) ; U3.V24 v1(42.11,56.01)
  L3 w0.104: v1(42.11,56.01) 42.51,56.43 42.51,62.29 47.2,66.98 52.5,66.98 55.79,70.27 55.79,82.02 55.17,82.65 54.15,82.65 v1(53.85,82.95)
  BOTTOM w0.127: M2.D4 v1(53.85,82.95)
FBA_WCK67#: length 38.7
  TOP w0.127: U3.V25 v1(42.08,56.8) ; M2.D5 v1(53.85,82.15)
  L3 w0.104: v1(42.08,56.8) 42.3,57.02 42.3,57.26 42.19,57.37 42.01,57.37 41.91,57.47 41.91,57.68 42.01,57.78 42.19,57.78 42.3,57.89 42.3,61.22 42.19,61.33 42.01,61.33 41.91,61.43 41.91,61.64 42.01,61.74 42.19,61.74 42.3,61.85 42.3,62.37 47.11,67.19 52.41,67.19 55.58,70.36 55.58,81.94 55.08,82.44 54.14,82.44 v1(53.85,82.15)
  BOTTOM w0.127: v1(53.85,82.15) 53.85,82.15 M2.D5
FBVDD: length 277.8
  TOP w0.203: M1.L1 33.12,80.08 32.47,80.08 M1.L2
  TOP w0.25: v1(32.83,46.93) 32.83,46.94 32.52,47.25 U3.F14 ; v1(36.56,58.53) 36.56,57.54 36.7,57.4 U3.L26
  TOP w0.305: v1(31.63,58.5) 31.63,57.3 U3.E26 ; M1.C10 v1(25.6,73.37) ; M2.D14 v1(61.91,82.94) ; M1.B12 v1(24.79,73.35) ; M1.F14 v1(22.28,75.75) ; M2.G14 v1(61.95,80.55) ; M1.L1 33.33,80.29 v1(33.74,80.29) ; v1(32.81,76.55) M1.F1 v1(33.75,76.16) ; v1(32.81,76.55) M1.G1 v1(33.75,76.94) ; v1(32.81,76.55) M1.G2 v1(32.01,76.57) M1.F3 ; M1.D1 v1(33.75,74.56) ; M1.K12 v1(23.99,79.76) M1.L13 ; v1(51.44,82.16) M2.D1 v1(50.49,82.56) ; v1(53.05,78.15) M2.K3 v1(53.04,77.35) M2.L4 ; M2.G1 v1(50.49,80.17) 50.24,80.43 49.38,80.43 ; U3.G13 33.31,46.46 32.84,46.93 v1(32.83,46.93) ; M2.N5 v1(54.67,75.77) ; R753.1 12.61,82.17 12.8,81.98 ; M2.T3 v1(53.04,73.35) ; M1.P3 v1(31.99,82.95) ; U3.L24 v1(36.31,55.2) ; M2.L1 v1(50.48,76.95) ; v1(35.43,52.94) 35.21,53.16 U3.J21 ; M2.K12 v1(59.46,77.36) M2.L11 ; M1.D12 v1(24.8,74.15) M1.D11 v1(25.6,74.96) M1.E10 ; M1.E5 v1(29.57,75.71) ; M1.H3 v1(31.2,78.14) ; M2.M12 v1(59.45,75.75) ; v1(50.49,72.95) M2.T1 v1(51.45,73.35) ; v1(52.26,74.16) M2.P3 v1(53.04,74.96) ; M2.E10 v1(58.64,82.15) M2.D11 v1(59.45,82.96) M2.D12 ; v1(32.92,48.55) 33.32,48.14 U3.G15 ; M1.R10 v1(25.6,83.76) ; M1.L14 v1(22.23,80.16) ; 49.38,74.5 49.45,74.57 v1(49.9,74.57) v1(50.49,74.56) M2.P1 ; M2.B1 v1(50.49,84.16) ; M1.M1 v1(33.75,80.95) ; M1.T1 v1(33.75,84.16) ; M2.H3 v1(53.05,79.75) M2.G4 ; M2.B3 v1(53.03,84.55) ; M2.C5 v1(53.85,83.76) ; v1(33.62,48.57) 33.32,48.86 U3.G16 ; M1.K3 v1(31.2,78.96) ; M1.N5 v1(29.57,81.34) ; U3.H24 v1(33.82,55.99) ; M1.D3 v1(31.2,74.15) ; M2.M1 v1(50.49,76.16) ; U3.H26 v1(34.22,58.09) ; M1.T14 v1(22.24,84.16) ; M1.B3 v1(31.21,72.56) ; M2.B14 v1(61.92,84.55) ; 12.8,81.44 12.8,81.98 ; 12.8,81.98 13.34,81.98 ; 12.8,81.98 13.08,81.7 ; M1.G4 30.81,76.96 v1(31.2,77.34) ; M2.C10 v1(58.65,83.74) ; M2.R10 v1(58.65,73.35) ; M2.G11 v1(59.45,79.76) ; U3.G14 33.32,47.31 v1(32.92,47.72) ; M1.R5 v1(29.56,83.79) ; M2.M3 v1(52.25,76.54) M2.L2 ; M2.G2 v1(52.26,80.56) M2.F3 ; M2.H12 v1(60.23,79.76) M2.G13 M2.F12 v1(59.44,81.34) ; v1(25.59,80.56) M1.L11 M1.M12 v1(24.79,81.36) ; v1(24.8,75.77) M1.F12 M1.G13 24.01,77.35 v1(24.01,77.36) 24.02,77.36 M1.H12 v1(24.8,77.35) M1.G11 ; M2.P11 v1(58.65,74.95) M2.N10 v1(57.82,74.95) ; M2.F1 v1(50.5,80.96) ; M2.F14 v1(61.97,81.36) 62.34,80.98 ; M2.R5 v1(54.69,73.32) ; M2.L13 v1(61.04,77.36) ; M2.P14 v1(62,74.56) ; M2.B12 v1(59.45,83.76) ; M1.M3 v1(31.2,80.56) M1.L4 v1(31.2,79.76) ; v1(23.2,80.57) M1.M14 v1(22.23,80.95) ; M1.B14 v1(22.32,72.56) ; M2.M14 v1(62,76.16) ; M1.B1 v1(33.75,72.95) ; M1.C5 v1(30.4,73.35) ; U3.C25 v1(29.68,56.8) U3.B26 v1(29.68,57.6) ; M1.P12 v1(24.8,82.95) M1.P11 v1(25.6,82.16) M1.N10 v1(26.41,82.15) ; M2.L14 v1(62,76.95) ; M2.E5 v1(54.68,81.4) ; v1(62,72.95) M2.T14 ; v1(35.67,79.54) 35.38,79.93 R200.2 ; M1.T12 24.4,84.16 v1(24.8,83.76) ; M2.P12 v1(59.45,74.16) ; M1.D14 v1(22.33,74.16) ; M1.P14 v1(22.24,82.56) ; M2.D3 v1(52.25,82.16) ; M2.T12 v1(59.45,73.35) ; M1.G14 v1(22.29,76.55) ; M1.P1 v1(33.75,82.56) ; M1.T3 v1(32,84.56) ; U3.E23 v1(31.33,55.14)
  TOP w0.406: 48.18,84.83 47.55,84.83 ; 48.18,84.83 47.74,85.27 ; 48.18,84.83 47.59,84.23 ; 48.18,84.83 C630.2 ; C748.2 49.38,80.43 ; C682.1 62.38,80.94 62.34,80.98 ; R201.2 47.62,78.32 v1(47.54,78.4) ; 49.38,74.5 49.11,74.22 C623.2 ; C631.1 v1(29.65,87.49) ; C629.1 54.66,87.04 v1(54.34,87.36) ; v1(50.08,87.24) 50.23,87.09 C637.1 ; C681.1 57.55,87.94 v1(57.28,88.22) ; C560.1 v1(25.2,87.41)
  TOP w0.508: C683.1 63.37,75.34 66.26,78.22 v1(66.26,78.85)
  L3 w0.2: v1(53.05,78.15) 53.04,78.14 v1(53.04,77.35)
  L6 w0.305: v1(14.45,71.06) 15.25,70.26 15.25,31.3 v1(14,30.05)
  L6 w0.406: v1(9.7,28.41) 9.7,42.66 13.5,46.46 v1(13.5,69.46)
  BOTTOM w0.305: v1(53.04,73.35) M2.T3 ; M2.M12 v1(59.45,75.75) ; M1.M1 v1(33.75,80.96) ; v1(29.56,83.79) 29.61,83.79 30,83.41 M1.R5 29.94,83.37 29.53,83.11 v1(29.52,83.05) ; v1(57.82,74.95) M2.N10 v1(58.65,74.95) M2.P11 v1(59.45,74.16) M2.P12 ; M1.T3 v1(32,84.56) ; M1.G2 v1(32.81,76.55) ; v1(32.81,76.55) M1.G1 v1(33.75,76.94) ; v1(32.81,76.55) M1.F1 v1(33.75,76.16) ; M1.D1 v1(33.75,74.56) ; M2.M1 v1(50.49,76.16) ; M2.F3 v1(52.26,80.56) M2.G2 ; M2.B14 v1(61.92,84.55) ; M1.B1 v1(33.75,72.95) ; M1.F3 v1(32.01,76.57) ; M2.N5 v1(54.67,75.77) ; M2.P14 v1(62,74.56) ; v1(24.01,77.36) M1.H12 v1(24.8,77.35) M1.G11 ; v1(9.7,28.41) 9.62,28.49 R702.1 ; M2.D14 v1(61.91,82.94) ; M2.M14 v1(62,76.16) ; M2.R5 v1(54.69,73.32) ; v1(53.04,74.96) M2.P3 v1(52.26,74.16) ; M2.C5 v1(53.85,83.76) ; M1.K3 v1(31.2,79.76) M1.L4 v1(31.2,80.56) M1.M3 ; M2.B12 v1(59.45,83.76) ; M2.E10 v1(58.64,82.15) M2.D11 v1(59.45,82.96) M2.D12 ; v1(53.05,76.55) M2.M3 v1(52.25,76.54) M2.L2 ; M1.G4 v1(31.2,77.34) M1.H3 ; U37.3 13.49,31.81 14,31.3 v1(14,30.05) ; M2.T12 v1(59.45,73.35) ; M2.G4 v1(53.05,79.75) M2.H3 v1(53.05,78.96) ; M2.L11 v1(59.46,77.36) M2.K12 ; M2.L4 v1(53.04,77.35) M2.K3 v1(53.05,78.15) ; M2.F14 v1(61.97,81.36) ; M2.L1 v1(50.48,76.95) ; M2.G11 v1(59.45,79.76) ; M1.D12 v1(24.8,74.15) M1.D11 v1(25.6,74.96) M1.E10 ; M1.T1 v1(33.75,84.16) ; M1.L1 v1(33.74,80.29) ; M2.L14 v1(62,76.95) ; M1.L2 v1(32.79,80.55) ; M1.B14 v1(22.32,72.56) ; M1.E5 v1(29.57,75.71) ; M1.P1 v1(33.75,82.56) ; M1.B12 v1(24.79,73.35) ; v1(59.44,81.34) M2.F12 M2.G13 v1(60.23,79.76) M2.H12 ; M1.N5 v1(29.57,81.34) ; M1.C5 v1(30.4,73.35) ; M2.T14 v1(62,72.95) ; M2.B1 v1(50.49,84.16) ; M1.P3 v1(31.99,82.95) ; M2.G14 v1(61.95,80.55) ; M2.C10 v1(58.65,83.74) ; M2.L13 v1(61.04,77.36)
  BOTTOM w0.35: M1.D3 31.6,74.55 v1(31.2,74.15) ; M2.B3 52.65,84.14 v1(53.03,84.55) ; M1.D14 v1(22.33,74.16)
  BOTTOM w0.4: v1(25.59,80.56) 25.2,80.16 M1.L11 ; M1.F12 24.41,76.16 v1(24.8,75.77) ; v1(24.8,83.76) 24.79,83.76 M1.T12 ; M2.R10 58.25,73.75 v1(58.65,73.35) ; M1.P12 v1(24.8,82.95) ; M1.F14 22.68,76.16 v1(22.28,75.75)
  BOTTOM w0.406: C636.1 21.26,72.75 v1(21.49,72.52) 22.29,72.52 v1(22.32,72.56) ; M1.G13 M1.F12 ; v1(22.33,74.16) 22.14,73.97 C557.1 ; M1.T14 v1(22.24,84.16) 22.08,84.31 C555.1 ; M1.L13 v1(23.99,79.76) M1.K12 ; v1(24.8,82.95) M1.P11 ; M2.D3 v1(52.25,82.16) ; C579.1 49.61,80.95 v1(50.49,80.95) M2.F1 ; M1.G14 v1(22.29,76.55) 21.93,76.2 C556.1 ; M2.E5 v1(54.68,81.4) ; v1(26.41,82.15) M1.N10 v1(25.6,82.16) ; M2.G1 v1(50.49,80.17) 49.56,80.17 C599.1 ; v1(50.48,76.95) 49.62,76.95 C580.1 ; M1.M12 v1(24.79,81.36) ; M1.M14 v1(22.23,80.95) ; v1(27.72,56.06) 26.36,56.06 R246.1 R194.2 ; C554.1 22.17,82.48 v1(22.24,82.56) M1.P14 ; v1(51.45,73.35) 51.05,72.96 M2.T1 v1(50.5,72.96) 49.33,72.95 C745.1 ; M1.L14 v1(22.23,80.16) ; M1.R10 v1(25.6,83.76) ; C597.1 49.4,82.72 50.33,82.72 v1(50.49,82.56) M2.D1 v1(51.44,82.16) ; M1.C10 v1(25.6,73.37) ; M1.B3 v1(31.21,72.56) ; C581.1 49.73,74.74 v1(49.9,74.57) 50.48,74.57 v1(50.49,74.56) M2.P1
  vias: v1(18.91,86.86) v1(18.94,86.24) v1(19.56,86.86) v1(19.58,86.24) v1(20.21,86.26) v1(20.22,86.85) v1(20.82,86.84) v1(23.18,73.35) v1(28.88,53.49) v1(29.55,82.1) v1(30.4,78.96) v1(30.4,71.76) v1(30.49,48.54) v1(32.8,83.77) v1(32.79,82.16) v1(32.9,51.85) v1(33.87,51.8) v1(35.47,53.56) v1(36.33,53.53) v1(37.12,53.55) v1(40.43,57.59) v1(40.43,52.75) v1(41.24,53.59) v1(43.66,52.72) v1(43.73,54.36) v1(49.91,84.16) v1(54.69,75.02) v1(54.72,74.05) v1(60.26,76.55) v1(60.83,87.49) v1(61.92,87.51) v2(13.2,79.61) v2(13.26,81.26) v2(13.23,80.46) v2(14.11,79.61) v2(14.17,81.26) v2(14.15,80.46) v2(17.25,70.01) v2(17.25,69.23) v2(17.25,68.4) v2(17.25,67.52) v2(17.25,66.72) v2(18.16,70.01) v2(18.16,69.23) v2(18.16,68.4) v2(18.16,67.52) v2(18.16,66.72) v2(19.28,48.21) v2(20.05,47.12) v2(20.96,46.04) v2(38.7,86.85) v2(38.72,85.43) v2(38.79,84) v2(40.16,79.44) v2(40.13,78.26) v2(40.16,77.06) v2(40.55,86.91) v2(40.56,85.54) v2(41.99,79.43) v2(42.02,78.31) v2(42.04,77.15) v2(42.19,86.87) v2(42.27,85.63) v2(43.85,86.85) v2(43.89,85.65)
